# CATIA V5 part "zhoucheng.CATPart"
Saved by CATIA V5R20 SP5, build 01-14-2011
Part number: 轴承保持架
Bounding box of the stored display mesh (mm): x -100 to 100, y -99.999 to 99.999, z 0 to 19.749
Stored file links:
  E:\180522133\zhoucheng.CATPart
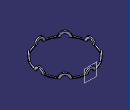
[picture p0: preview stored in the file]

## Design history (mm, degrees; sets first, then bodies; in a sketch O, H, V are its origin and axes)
Body1 (main body)
  Sketch1 on xy-plane, origin (0, 0, 0), H (1, 0, 0), V (0, 1, 0)
    circle A1 centre (0, 0) radius 100
    radius A1 = 100
  Pad1: profile Sketch1, direction (0, 0, 1), length 2.5, mirrored extent, thin wall 5
  Body2
    Sketch2 on xy-plane, origin (0, 0, 0), H (1, 0, 0), V (0, 1, 0)
      arc A1 centre (97.5, 0) radius 20 from (97.6062, -19.9997) to (97.6062, 19.9997) ccw
      point P1 (97.5, 0)
      axis line L1 (97.6062, 61.0413) -> (97.6062, -46.7387)
      point P4 (97.6062, 19.9997)
      point P5 (97.6062, -19.9997)
      distance O P1 = 97.5
      radius A1 = 20
      coincidence: P1 H, L1 P4, L1 P5
      vertical: L1 V
    Shaft1: profile Sketch2, axis Sketch2.L1, angle 360
    Sketch3 on xy-plane, origin (0, 0, 0), H (1, 0, 0), V (0, 1, 0)
      circle A1 centre (0, 0) radius 95
      radius A1 = 95
    CircPattern1: of Shaft1, instances 8, angular step 45, axis from end face of Pad1
    Pocket1: profile Sketch3, direction (0, 0, -1), length 20.5, mirrored extent
  Assemble1: tool Body2
  Sketch4 on xy-plane, origin (0, 0, 0), H (1, 0, 0), V (0, 1, 0)
    circle A1 centre (0, 0) radius 117.5648
  Pocket2: profile Sketch4, direction (0, 0, -1), length 60
  Sketch5 on xy-plane, origin (0, 0, 0), H (1, 0, 0), V (0, 1, 0)
    circle A1 centre (0, 0) radius 100
    radius A1 = 100
  Pocket3: profile Sketch5, direction (0, 0, -1), length 60, mirrored extent, outer side
  Body3
    Plane1: type Offset, RefPlane zx-plane, Offset 97.5
    Sketch6 on Plane1, origin (0, 97.5, 0), H (-1, 0, 0), V (0, 0, 1)
      arc A1 centre (0, 0) radius 12 from (-12, 0) to (12, 0) ccw
      axis line L1 (-119.7807, 0) -> (152.4261, 0)
      point P1 (-119.7807, 0)
      point P3 (-12, 0)
      point P4 (12, 0)
      radius A1 = 12
      coincidence: P1 H, L1 P4, L1 P3
      horizontal: L1 H
    Shaft2: profile Sketch6, axis Sketch6.L1, angle 360
    CircPattern2: of Shaft2, instances 8, angular step 45, axis from end face of Pad1
  Remove1: tool Body3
